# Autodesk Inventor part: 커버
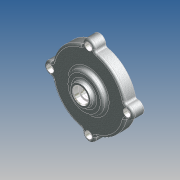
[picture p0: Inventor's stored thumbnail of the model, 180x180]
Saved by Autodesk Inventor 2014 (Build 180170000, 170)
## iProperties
Created: 2012-05
Part Number: 커버
Document SubType Name: 모델링
Designer: SeoGD™
Material: 일반
Appearance: 알루미늄 캐스트
변환 표준: STEP AP214IS
파일 이름: C:\Users\SeoGD\Desktop\?쒗뿕\而ㅻ쾭-1.stp
전처리기: Build: 253, Release: 2010 SP1 - Date: Wed 07/29/2009
전송 단위: 밀리미터
불확실성: 0.01
Author: SeoGD™
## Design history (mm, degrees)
sketch "스케치1"
  geometry: L1 (0, 0)-(0, 26); L2 (50, 0)-(50, 15); L3 (50, 15)-(25, 15); L4 (25, 15)-(25, 21); L5 (25, 21)-(15, 21); L6 (15, 21)-(13.66, 26); L7 (13.66, 26)-(10, 26); L8 (50, 0)-(45, 0); L9 (45, 0)-(45, 10); L10 (45, 10)-(14.5, 10); L11 (14.5, 10)-(13.266, 3); L12 (13.266, 3)-(11, 3); L13 (11, 3)-(11, 16); L14 (11, 16)-(7.5, 16); L15 (7.5, 16)-(7.5, 19); L16 (7.5, 19)-(10, 19); L17 (10, 19)-(10, 26)
  constraints: 34 end point, 10 parallel, 2 perpendicular, 2 point on line, 1 vertical
  dimensions: "d11" = 100 diameter of L2 L1; "d12" = 22 diameter of L13 L1; "d13" = 90 diameter of L9 L1; "d14" = 15 distance between parallel lines of L3 L8; "d15" = 10 distance between parallel lines of L8 L10; "d16" = 29 diameter of L10.end L1; "d17" = 100 deg angle of L11 L10; "d18" = 7 distance between parallel lines of L12 L10; "d19" = 13 distance between parallel lines of L14 L12; "d20" = 3 distance between parallel lines of L16 L14; "d21" = 15 diameter of L15 L1; "d22" = 20 diameter of L17 L1; "d23" = 30 diameter of L5.end L1; "d24" = 6 distance between parallel lines of L5 L3; "d25" = 50 diameter of L4 L1; "d26" = 105 deg angle of L5 L6; "d50" = 26 distance of L1.start L1.end
revolve "회전1" sketch "스케치1" stored, may be unused: angle "d27" = 90 deg
sketch "스케치2" dims "d29" = 104
  geometry: A1 r 8.5 centre (0, 52) between (8.074, 49.344) and (-8.074, 49.344); A2 r 50 centre (0, 0) between (-8.074, 49.344) and (8.074, 49.344) reference; 2 further points
  constraints: 4 point on circle, 2 vertical alignment, 1 centre point, 1 coincident, 2 other
  dimensions: "d28" = 17 diameter of A1
extrude "돌출1" join sketch "스케치2" stored distance "d30" = 10; taper "d31" = 0 deg
fillet "모깎기3" dims "d32" = 3
fillet "모깎기4" dims "d45" = 3, "d46" = 0.2
chamfer "모따기1" distance "d47" = 1; stored, may be unused: second distance "d48" = 2, angle "d49" = 45 deg
hole "구멍2" diameter "d38" = 5.5; stored, may be unused: countersink angle "d42" = 90 deg, drill point angle "d44" = 118 deg; dims "d36" = 10, "d37" = 10, "d39" = 6, "d40" = 9.5, "d41" = 5.4, "d43" = 8
node "솔리드1"
node "솔리드 본체"
node "곡면 본체"
pattern_circular "원형 패턴1" dims angle "d34" = 360 deg
pattern_circular "원형 패턴2" dims angle "d52" = 360 deg
node "솔리드2"
